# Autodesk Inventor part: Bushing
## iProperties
Shininess: 77.0
Length Units: 11269
Angle Units: 11279
Time Units: 11290
Mass Units: 11283
Length Display Precision: 3
Angle Display Precision: 2
Created: 2002-02
Part Number: Bushing
Document SubType Name: Modeling
Designer: ***
Density: 1 g/cm^3
Density: 0.0
Volumn: 0.0
Area: 0.0
PropertySet Name: Model Information
Control State: 0
Master: False
Checked Out: False
Author: ***
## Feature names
1. Revolution1
